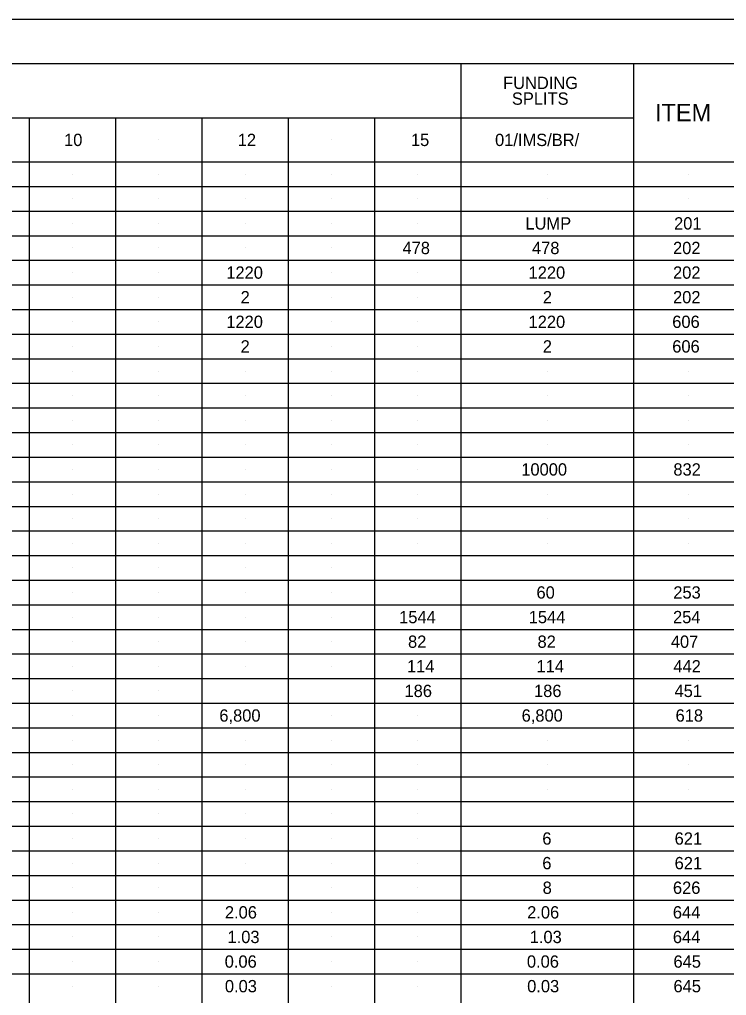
# Model space of a CAD drawing. Extents: x 1 to 35, y -2 to 20.
# Drawn here: x 9.79 to 17.83, y 8.94 to 20.04 of the extents above; entities that cross this region are included whole.
import ezdxf

# ---------------------------------------------------------------- set-up
doc = ezdxf.new("R2010")
doc.units = 0
for name, color, linetype in [('SH_Border', 7, 'Continuous'), ('SH_Cut_Line', 7, 'Continuous'), ('SH_Data', 7, 'Continuous'), ('SH_Text', 7, 'Continuous')]:
    doc.layers.add(name, color=color, linetype=linetype)

msp = doc.modelspace()

# ---------------------------------------------------------------- linework, layer by layer
at = {"layer": 'SH_Border'}
msp.add_lwpolyline([(3.031, 19.543), (34.531, 19.543), (34.531, -1.457), (3.031, -1.457)], close=True, dxfattribs=at)
at = {"layer": 'SH_Cut_Line'}
msp.add_lwpolyline([(1.031, -1.957), (35.031, -1.957), (35.031, 20.043), (1.031, 20.043)], close=True, dxfattribs=at)
at = {"layer": 'SH_Data'}
for p, q in [((14.817, -1.457), (14.817, 19.543)), ((16.781, -1.457), (16.781, 19.543)), ((3.031, 18.923), (16.781, 18.923)), ((9.906, -1.457), (9.906, 18.923)), ((10.888, -1.457), (10.888, 18.923)), ((11.87, -1.457), (11.87, 18.923)), ((12.852, -1.457), (12.852, 18.923)), ((13.835, -1.457), (13.835, 18.923)), ((10.397, 18.673), (10.397, 18.673)), ((11.379, 18.673), (11.379, 18.673)), ((12.361, 18.673), (12.361, 18.673)), ((13.343, 18.673), (13.343, 18.673)), ((14.326, 18.673), (14.326, 18.673)), ((15.799, 18.673), (15.799, 18.673)), ((3.031, 18.423), (33.531, 18.423)), ((10.397, 18.283), (10.397, 18.283)), ((11.379, 18.283), (11.379, 18.283)), ((12.361, 18.283), (12.361, 18.283)), ((13.343, 18.283), (13.343, 18.283)), ((14.326, 18.283), (14.326, 18.283)), ((15.799, 18.283), (15.799, 18.283)), ((17.406, 18.283), (17.406, 18.283)), ((3.031, 18.143), (33.531, 18.143)), ((10.397, 18.003), (10.397, 18.003)), ((11.379, 18.003), (11.379, 18.003)), ((12.361, 18.003), (12.361, 18.003)), ((13.343, 18.003), (13.343, 18.003)), ((14.326, 18.003), (14.326, 18.003)), ((15.799, 18.003), (15.799, 18.003)), ((15.799, 18.003), (15.799, 18.003)), ((17.406, 18.003), (17.406, 18.003)), ((3.031, 17.863), (33.531, 17.863)), ((10.397, 17.723), (10.397, 17.723)), ((11.379, 17.723), (11.379, 17.723)), ((12.361, 17.723), (12.361, 17.723)), ((13.343, 17.723), (13.343, 17.723)), ((14.326, 17.723), (14.326, 17.723)), ((15.799, 17.723), (15.799, 17.723)), ((15.799, 17.723), (15.799, 17.723)), ((17.406, 17.723), (17.406, 17.723)), ((3.031, 17.583), (33.531, 17.583)), ((10.397, 17.443), (10.397, 17.443)), ((11.379, 17.443), (11.379, 17.443)), ((12.361, 17.443), (12.361, 17.443)), ((13.343, 17.443), (13.343, 17.443)), ((14.326, 17.443), (14.326, 17.443)), ((15.799, 17.443), (15.799, 17.443)), ((15.799, 17.443), (15.799, 17.443)), ((17.406, 17.443), (17.406, 17.443)), ((3.031, 17.303), (33.531, 17.303)), ((10.397, 17.163), (10.397, 17.163)), ((11.379, 17.163), (11.379, 17.163)), ((12.361, 17.163), (12.361, 17.163)), ((13.343, 17.163), (13.343, 17.163)), ((14.326, 17.163), (14.326, 17.163)), ((15.799, 17.163), (15.799, 17.163)), ((15.799, 17.163), (15.799, 17.163)), ((17.406, 17.163), (17.406, 17.163)), ((3.031, 17.023), (33.531, 17.023)), ((10.397, 16.883), (10.397, 16.883)), ((11.379, 16.883), (11.379, 16.883)), ((12.361, 16.883), (12.361, 16.883)), ((13.343, 16.883), (13.343, 16.883)), ((14.326, 16.883), (14.326, 16.883)), ((15.799, 16.883), (15.799, 16.883)), ((15.799, 16.883), (15.799, 16.883)), ((17.406, 16.883), (17.406, 16.883)), ((3.031, 16.743), (33.531, 16.743)), ((10.397, 16.603), (10.397, 16.603)), ((11.379, 16.603), (11.379, 16.603)), ((12.361, 16.603), (12.361, 16.603)), ((13.343, 16.603), (13.343, 16.603)), ((14.326, 16.603), (14.326, 16.603)), ((15.799, 16.603), (15.799, 16.603)), ((15.799, 16.603), (15.799, 16.603)), ((17.406, 16.603), (17.406, 16.603)), ((3.031, 16.463), (33.531, 16.463)), ((10.397, 16.323), (10.397, 16.323)), ((11.379, 16.323), (11.379, 16.323)), ((12.361, 16.323), (12.361, 16.323)), ((13.343, 16.323), (13.343, 16.323)), ((14.326, 16.323), (14.326, 16.323)), ((15.799, 16.323), (15.799, 16.323)), ((15.799, 16.323), (15.799, 16.323)), ((17.406, 16.323), (17.406, 16.323)), ((3.031, 16.183), (33.531, 16.183)), ((10.397, 16.043), (10.397, 16.043)), ((11.379, 16.043), (11.379, 16.043)), ((12.361, 16.043), (12.361, 16.043)), ((13.343, 16.043), (13.343, 16.043)), ((14.326, 16.043), (14.326, 16.043)), ((15.799, 16.043), (15.799, 16.043)), ((15.799, 16.043), (15.799, 16.043)), ((17.406, 16.043), (17.406, 16.043)), ((3.031, 15.903), (33.531, 15.903)), ((10.397, 15.763), (10.397, 15.763)), ((11.379, 15.763), (11.379, 15.763)), ((12.361, 15.763), (12.361, 15.763)), ((13.343, 15.763), (13.343, 15.763)), ((14.326, 15.763), (14.326, 15.763)), ((15.799, 15.763), (15.799, 15.763)), ((15.799, 15.763), (15.799, 15.763)), ((17.406, 15.763), (17.406, 15.763)), ((3.031, 15.623), (33.531, 15.623)), ((10.397, 15.483), (10.397, 15.483)), ((11.379, 15.483), (11.379, 15.483)), ((12.361, 15.483), (12.361, 15.483)), ((13.343, 15.483), (13.343, 15.483)), ((14.326, 15.483), (14.326, 15.483)), ((15.799, 15.483), (15.799, 15.483)), ((15.799, 15.483), (15.799, 15.483)), ((17.406, 15.483), (17.406, 15.483)), ((3.031, 15.343), (33.531, 15.343)), ((10.397, 15.203), (10.397, 15.203)), ((11.379, 15.203), (11.379, 15.203)), ((12.361, 15.203), (12.361, 15.203)), ((13.343, 15.203), (13.343, 15.203)), ((14.326, 15.203), (14.326, 15.203)), ((15.799, 15.203), (15.799, 15.203)), ((15.799, 15.203), (15.799, 15.203)), ((17.406, 15.203), (17.406, 15.203)), ((3.031, 15.063), (33.531, 15.063)), ((10.397, 14.923), (10.397, 14.923)), ((11.379, 14.923), (11.379, 14.923)), ((12.361, 14.923), (12.361, 14.923)), ((13.343, 14.923), (13.343, 14.923)), ((14.326, 14.923), (14.326, 14.923)), ((15.799, 14.923), (15.799, 14.923)), ((15.799, 14.923), (15.799, 14.923)), ((17.406, 14.923), (17.406, 14.923)), ((3.031, 14.783), (33.531, 14.783)), ((10.397, 14.643), (10.397, 14.643)), ((11.379, 14.643), (11.379, 14.643)), ((12.361, 14.643), (12.361, 14.643)), ((13.343, 14.643), (13.343, 14.643)), ((14.326, 14.643), (14.326, 14.643)), ((15.799, 14.643), (15.799, 14.643)), ((15.799, 14.643), (15.799, 14.643)), ((17.406, 14.643), (17.406, 14.643)), ((3.031, 14.503), (33.531, 14.503)), ((10.397, 14.363), (10.397, 14.363)), ((11.379, 14.363), (11.379, 14.363)), ((12.361, 14.363), (12.361, 14.363)), ((13.343, 14.363), (13.343, 14.363)), ((14.326, 14.363), (14.326, 14.363)), ((15.799, 14.363), (15.799, 14.363)), ((15.799, 14.363), (15.799, 14.363)), ((17.406, 14.363), (17.406, 14.363)), ((3.031, 14.223), (33.531, 14.223)), ((10.397, 14.083), (10.397, 14.083)), ((11.379, 14.083), (11.379, 14.083)), ((12.361, 14.083), (12.361, 14.083)), ((13.343, 14.083), (13.343, 14.083)), ((14.326, 14.083), (14.326, 14.083)), ((15.799, 14.083), (15.799, 14.083)), ((15.799, 14.083), (15.799, 14.083)), ((17.406, 14.083), (17.406, 14.083)), ((3.031, 13.943), (33.531, 13.943)), ((10.397, 13.803), (10.397, 13.803)), ((11.379, 13.803), (11.379, 13.803)), ((12.361, 13.803), (12.361, 13.803)), ((13.343, 13.803), (13.343, 13.803)), ((3.031, 13.663), (33.531, 13.663)), ((10.397, 13.523), (10.397, 13.523)), ((11.379, 13.523), (11.379, 13.523)), ((12.361, 13.523), (12.361, 13.523)), ((13.343, 13.523), (13.343, 13.523)), ((3.031, 13.383), (33.531, 13.383)), ((10.397, 13.243), (10.397, 13.243)), ((11.379, 13.243), (11.379, 13.243)), ((12.361, 13.243), (12.361, 13.243)), ((13.343, 13.243), (13.343, 13.243)), ((14.326, 13.243), (14.326, 13.243)), ((15.799, 13.243), (15.799, 13.243)), ((15.799, 13.243), (15.799, 13.243)), ((17.406, 13.243), (17.406, 13.243)), ((3.031, 13.103), (33.531, 13.103)), ((10.397, 12.963), (10.397, 12.963)), ((11.379, 12.963), (11.379, 12.963)), ((12.361, 12.963), (12.361, 12.963)), ((13.343, 12.963), (13.343, 12.963)), ((14.326, 12.963), (14.326, 12.963)), ((15.799, 12.963), (15.799, 12.963)), ((15.799, 12.963), (15.799, 12.963)), ((17.406, 12.963), (17.406, 12.963)), ((3.031, 12.823), (33.531, 12.823)), ((10.397, 12.683), (10.397, 12.683)), ((11.379, 12.683), (11.379, 12.683)), ((12.361, 12.683), (12.361, 12.683)), ((13.343, 12.683), (13.343, 12.683)), ((14.326, 12.683), (14.326, 12.683)), ((15.799, 12.683), (15.799, 12.683)), ((15.799, 12.683), (15.799, 12.683)), ((17.406, 12.683), (17.406, 12.683)), ((3.031, 12.543), (33.531, 12.543)), ((10.397, 12.403), (10.397, 12.403)), ((11.379, 12.403), (11.379, 12.403)), ((14.326, 12.403), (14.326, 12.403)), ((15.799, 12.403), (15.799, 12.403)), ((15.799, 12.403), (15.799, 12.403)), ((17.406, 12.403), (17.406, 12.403)), ((3.031, 12.263), (33.531, 12.263)), ((10.397, 12.123), (10.397, 12.123)), ((11.379, 12.123), (11.379, 12.123)), ((12.361, 12.123), (12.361, 12.123)), ((12.361, 12.123), (12.361, 12.123)), ((13.343, 12.123), (13.343, 12.123)), ((13.343, 12.123), (13.343, 12.123)), ((14.326, 12.123), (14.326, 12.123)), ((14.326, 12.123), (14.326, 12.123)), ((15.799, 12.123), (15.799, 12.123)), ((15.799, 12.123), (15.799, 12.123)), ((15.799, 12.123), (15.799, 12.123)), ((15.799, 12.123), (15.799, 12.123)), ((17.406, 12.123), (17.406, 12.123)), ((17.406, 12.123), (17.406, 12.123)), ((3.031, 11.983), (33.531, 11.983)), ((10.397, 11.843), (10.397, 11.843)), ((11.379, 11.843), (11.379, 11.843)), ((12.361, 11.843), (12.361, 11.843)), ((13.343, 11.843), (13.343, 11.843)), ((14.326, 11.843), (14.326, 11.843)), ((15.799, 11.843), (15.799, 11.843)), ((15.799, 11.843), (15.799, 11.843)), ((17.406, 11.843), (17.406, 11.843)), ((3.031, 11.703), (33.531, 11.703)), ((10.397, 11.563), (10.397, 11.563)), ((11.379, 11.563), (11.379, 11.563)), ((12.361, 11.563), (12.361, 11.563)), ((13.343, 11.563), (13.343, 11.563)), ((14.326, 11.563), (14.326, 11.563)), ((15.799, 11.563), (15.799, 11.563)), ((15.799, 11.563), (15.799, 11.563)), ((17.406, 11.563), (17.406, 11.563)), ((3.031, 11.423), (33.531, 11.423)), ((10.397, 11.283), (10.397, 11.283)), ((11.379, 11.283), (11.379, 11.283)), ((12.361, 11.283), (12.361, 11.283)), ((13.343, 11.283), (13.343, 11.283)), ((14.326, 11.283), (14.326, 11.283)), ((15.799, 11.283), (15.799, 11.283)), ((15.799, 11.283), (15.799, 11.283)), ((17.406, 11.283), (17.406, 11.283)), ((3.031, 11.143), (33.531, 11.143)), ((10.397, 11.003), (10.397, 11.003)), ((11.379, 11.003), (11.379, 11.003)), ((12.361, 11.003), (12.361, 11.003)), ((13.343, 11.003), (13.343, 11.003)), ((14.326, 11.003), (14.326, 11.003)), ((3.031, 10.863), (33.531, 10.863)), ((10.397, 10.723), (10.397, 10.723)), ((11.379, 10.723), (11.379, 10.723)), ((12.361, 10.723), (12.361, 10.723)), ((13.343, 10.723), (13.343, 10.723)), ((14.326, 10.723), (14.326, 10.723)), ((15.799, 10.723), (15.799, 10.723)), ((15.799, 10.723), (15.799, 10.723)), ((17.406, 10.723), (17.406, 10.723)), ((3.031, 10.583), (33.531, 10.583)), ((10.397, 10.443), (10.397, 10.443)), ((11.379, 10.443), (11.379, 10.443)), ((12.361, 10.443), (12.361, 10.443)), ((13.343, 10.443), (13.343, 10.443)), ((14.326, 10.443), (14.326, 10.443)), ((15.799, 10.443), (15.799, 10.443)), ((15.799, 10.443), (15.799, 10.443)), ((17.406, 10.443), (17.406, 10.443)), ((3.031, 10.303), (33.531, 10.303)), ((10.397, 10.163), (10.397, 10.163)), ((11.379, 10.163), (11.379, 10.163)), ((13.343, 10.163), (13.343, 10.163)), ((14.326, 10.163), (14.326, 10.163)), ((15.799, 10.163), (15.799, 10.163)), ((15.799, 10.163), (15.799, 10.163)), ((17.406, 10.163), (17.406, 10.163)), ((3.031, 10.023), (33.531, 10.023)), ((10.397, 9.883), (10.397, 9.883)), ((11.379, 9.883), (11.379, 9.883)), ((12.361, 9.883), (12.361, 9.883)), ((13.343, 9.883), (13.343, 9.883)), ((14.326, 9.883), (14.326, 9.883)), ((15.799, 9.883), (15.799, 9.883)), ((15.799, 9.883), (15.799, 9.883)), ((17.406, 9.883), (17.406, 9.883)), ((3.031, 9.743), (33.531, 9.743)), ((10.397, 9.603), (10.397, 9.603)), ((11.379, 9.603), (11.379, 9.603)), ((12.361, 9.603), (12.361, 9.603)), ((13.343, 9.603), (13.343, 9.603)), ((14.326, 9.603), (14.326, 9.603)), ((15.799, 9.603), (15.799, 9.603)), ((15.799, 9.603), (15.799, 9.603)), ((17.406, 9.603), (17.406, 9.603)), ((3.031, 9.463), (33.531, 9.463)), ((10.397, 9.323), (10.397, 9.323)), ((11.379, 9.323), (11.379, 9.323)), ((12.361, 9.323), (12.361, 9.323)), ((13.343, 9.323), (13.343, 9.323)), ((14.326, 9.323), (14.326, 9.323)), ((15.799, 9.323), (15.799, 9.323)), ((15.799, 9.323), (15.799, 9.323)), ((17.406, 9.323), (17.406, 9.323)), ((3.031, 9.183), (33.531, 9.183)), ((10.397, 9.043), (10.397, 9.043)), ((11.379, 9.043), (11.379, 9.043)), ((12.361, 9.043), (12.361, 9.043)), ((12.361, 9.043), (12.361, 9.043)), ((13.343, 9.043), (13.343, 9.043)), ((14.326, 9.043), (14.326, 9.043)), ((15.799, 9.043), (15.799, 9.043)), ((15.799, 9.043), (15.799, 9.043)), ((15.799, 9.043), (15.799, 9.043)), ((15.799, 9.043), (15.799, 9.043)), ((17.406, 9.043), (17.406, 9.043)), ((17.406, 9.043), (17.406, 9.043))]:
    msp.add_line(p, q, dxfattribs=at)

# ---------------------------------------------------------------- texts
for s, height, p in [('FUNDING', 0.14, (15.294, 19.252)), ('SPLITS', 0.14, (15.394, 19.073)), ('ITEM', 0.2, (17.022, 18.883))]:
    msp.add_text(s, height=height, dxfattribs=at).set_placement(p)
at = {"layer": 'SH_Text'}
for s, p in [('10', (10.301, 18.603)), ('12', (12.276, 18.603)), ('15', (14.246, 18.603)), ('01/IMS/BR/', (15.203, 18.603)), ('LUMP', (15.548, 17.653)), ('201', (17.239, 17.653)), ('478', (14.15, 17.373)), ('478', (15.623, 17.373)), ('202', (17.227, 17.373)), ('1220', (12.146, 17.093)), ('1220', (15.584, 17.093)), ('202', (17.227, 17.093)), ('2', (12.309, 16.813)), ('2', (15.746, 16.813)), ('202', (17.227, 16.813)), ('1220', (12.146, 16.533)), ('1220', (15.584, 16.533)), ('606', (17.218, 16.533)), ('2', (12.309, 16.253)), ('2', (15.746, 16.253)), ('606', (17.218, 16.253)), ('10000', (15.501, 14.853)), ('832', (17.231, 14.853)), ('60', (15.674, 13.453)), ('253', (17.23, 13.453)), ('1544', (14.112, 13.173)), ('1544', (15.586, 13.173)), ('254', (17.227, 13.173)), ('82', (14.213, 12.893)), ('82', (15.686, 12.893)), ('407', (17.202, 12.893)), ('114', (14.201, 12.613)), ('114', (15.674, 12.613)), ('442', (17.231, 12.613)), ('186', (14.173, 12.333)), ('186', (15.646, 12.333)), ('451', (17.244, 12.333)), ('6,800', (12.067, 12.053)), ('6,800', (15.505, 12.053)), ('618', (17.256, 12.053)), ('6', (15.74, 10.653)), ('621', (17.245, 10.653)), ('6', (15.74, 10.373)), ('621', (17.245, 10.373)), ('8', (15.744, 10.093)), ('626', (17.226, 10.093)), ('2.06', (12.13, 9.813)), ('2.06', (15.568, 9.813)), ('644', (17.225, 9.813)), ('1.03', (12.16, 9.533)), ('1.03', (15.597, 9.533)), ('644', (17.225, 9.533)), ('0.06', (12.128, 9.253)), ('0.06', (15.565, 9.253)), ('645', (17.232, 9.253)), ('0.03', (12.13, 8.973)), ('0.03', (15.568, 8.973)), ('645', (17.232, 8.973))]:
    msp.add_text(s, height=0.14, dxfattribs=at).set_placement(p)

doc.saveas('drawing.dxf')
